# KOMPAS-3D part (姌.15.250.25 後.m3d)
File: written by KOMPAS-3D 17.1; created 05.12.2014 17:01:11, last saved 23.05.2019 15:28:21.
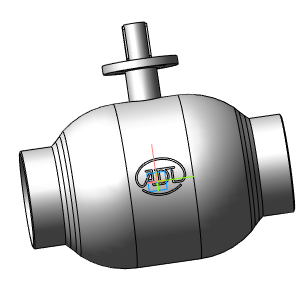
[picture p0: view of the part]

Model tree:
1. Операция без истории:4  (labels: Сталь 20  ГОСТ 1050-88)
